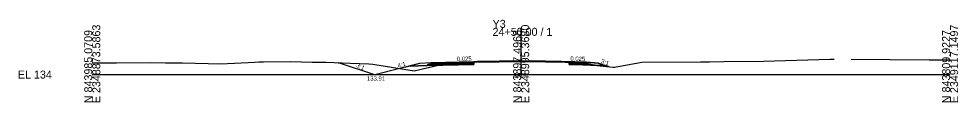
# Model space of a CAD drawing. Extents: x -26 to 2349107, y -10 to 844057.
# Drawn here: x -25.7 to 302.8, y 3490.3 to 3519.2 of the extents above; entities that cross this region are included whole.
import ezdxf

# ---------------------------------------------------------------- set-up
doc = ezdxf.new("R2010")
doc.units = 0
for name, color, linetype in [('Exist Cross Section Cell', 7, 'Continuous'), ('Exist XS Center Line Elevation Label', 7, 'Continuous'), ('Exist XS Ground Line', 7, 'Continuous'), ('Prop CMT Pvmt Course 1', 7, 'Continuous'), ('Prop CMT Pvmt Course 2', 7, 'Continuous'), ('Prop CMT Pvmt Course 3', 7, 'Continuous'), ('Prop CMT Pvmt Surface Shoulder', 7, 'Continuous'), ('Prop CMT Shld Paved Course 1', 7, 'Continuous'), ('Prop CMT Shld Paved Course 2', 7, 'Continuous'), ('Prop CMT Shld Paved Course 3', 7, 'Continuous'), ('Prop CMT Slope Grass', 7, 'Continuous'), ('Prop CMT Subgrade Earthwork', 7, 'Continuous'), ('Prop XS Ditch Standard Text', 7, 'Continuous'), ('Prop XS Earthwork Shape', 7, 'Continuous'), ('Prop XS SE Text', 7, 'Continuous'), ('Prop XS Side Slope Text', 7, 'Continuous')]:
    doc.layers.add(name, color=color, linetype=linetype)

msp = doc.modelspace()

# ---------------------------------------------------------------- linework, layer by layer
at = {"layer": 'Exist Cross Section Cell'}
for p, q in [((150, 3500), (150, 3516.36)), ((0, 3500), (150, 3500)), ((150, 3500), (300, 3500))]:
    msp.add_line(p, q, dxfattribs=at)
at = {"layer": 'Exist XS Ground Line'}
for points in [[(0, 3504.1), (6.44, 3504.1), (7.88, 3504.1), (8.44, 3504.1), (20.2, 3504.21), (25.57, 3504.17), (31.52, 3504.07), (44.99, 3503.75), (56.84, 3504.37), (58.27, 3504.46), (59.83, 3504.49), (69.47, 3504.56), (76.96, 3504.39), (81.78, 3504.33), (90.23, 3504.01), (96.69, 3503.79), (98.1, 3503.59), (112.58, 3501.32), (115.04, 3501.88), (122.59, 3503.67), (127.37, 3504.1), (129.08, 3504.29), (129.86, 3504.29), (131.71, 3504.36), (133.64, 3504.4), (134.74, 3504.42), (135.96, 3504.44), (137.7, 3504.46), (138.76, 3504.48), (140.26, 3504.5), (140.79, 3504.51), (142.36, 3504.51), (144.17, 3504.53), (144.55, 3504.54), (146.95, 3504.56), (147.66, 3504.57), (148.88, 3504.57), (150.02, 3504.57), (153.09, 3504.56), (156.16, 3504.54), (156.66, 3504.54), (157.37, 3504.53), (158.46, 3504.51), (159.26, 3504.5), (160.27, 3504.48), (161.66, 3504.45), (162.37, 3504.44), (164.11, 3504.41), (165.4, 3504.39), (165.7, 3504.39), (166.75, 3504.36), (167.07, 3504.36), (168.45, 3504.34), (169.18, 3504.32), (170.03, 3504.28), (170.77, 3504.26), (172.3, 3503.84), (173.28, 3503.68), (176.43, 3503.2), (182.18, 3502.63), (182.68, 3502.59), (192.18, 3504.31), (212.67, 3504.43), (213.32, 3504.44), (215.86, 3504.52), (220.84, 3504.63), (234.78, 3504.71), (257.93, 3505.43), (259.42, 3505.45)], [(265.41, 3505.44), (292.69, 3505.17), (300, 3505.15)]]:
    msp.add_lwpolyline(points, dxfattribs=at)
at = {"layer": 'Prop CMT Pvmt Course 1'}
for p, q in [((122.5, 3504.24), (122.5, 3503.99)), ((133.43, 3504.52), (133.43, 3504.27)), ((166.75, 3504.48), (166.75, 3504.23)), ((168.74, 3504.43), (168.74, 3504.18))]:
    msp.add_line(p, q, dxfattribs=at)
at = {"layer": 'Prop CMT Pvmt Course 2'}
for p, q in [((122.5, 3503.99), (122.5, 3503.66)), ((133.43, 3504.27), (133.43, 3503.93)), ((166.75, 3504.23), (166.75, 3503.9)), ((168.74, 3504.18), (168.74, 3503.85))]:
    msp.add_line(p, q, dxfattribs=at)
at = {"layer": 'Prop CMT Pvmt Course 3'}
for p, q in [((122.5, 3503.66), (122.5, 3503.29)), ((133.43, 3503.93), (133.43, 3503.56)), ((166.75, 3503.9), (166.75, 3503.53)), ((168.74, 3503.85), (168.74, 3503.48))]:
    msp.add_line(p, q, dxfattribs=at)
at = {"layer": 'Prop CMT Pvmt Surface Shoulder'}
for p, q in [((133.43, 3504.52), (118.5, 3504.14)), ((166.75, 3504.48), (168.74, 3504.43)), ((168.74, 3504.43), (172.9, 3504.33))]:
    msp.add_line(p, q, dxfattribs=at)
msp.add_lwpolyline([(133.43, 3504.52), (133.64, 3504.52), (134.74, 3504.54), (135.96, 3504.56), (137.7, 3504.59), (138.76, 3504.61), (140.26, 3504.63), (140.79, 3504.63), (142.35, 3504.64), (144.17, 3504.66), (144.55, 3504.66), (146.95, 3504.69), (147.66, 3504.69), (148.88, 3504.69), (150.02, 3504.69), (153.09, 3504.69), (156.16, 3504.67), (156.67, 3504.66), (157.37, 3504.65), (158.47, 3504.64), (159.26, 3504.63), (160.27, 3504.61), (161.66, 3504.58), (162.37, 3504.56), (164.11, 3504.54), (165.4, 3504.52), (165.7, 3504.51), (166.75, 3504.48)], dxfattribs=at)
at = {"layer": 'Prop CMT Shld Paved Course 1'}
for p, q in [((118.24, 3503.89), (133.43, 3504.27)), ((118.5, 3504.14), (118.24, 3503.89)), ((133.43, 3504.52), (118.5, 3504.14)), ((122.5, 3503.99), (122.5, 3504.24)), ((133.43, 3504.27), (133.43, 3504.52)), ((166.75, 3504.48), (168.74, 3504.43)), ((166.75, 3504.23), (166.75, 3504.48)), ((168.74, 3504.18), (166.75, 3504.23)), ((168.74, 3504.18), (168.74, 3504.43)), ((168.74, 3504.43), (172.9, 3504.33)), ((173.16, 3504.07), (168.74, 3504.18)), ((172.9, 3504.33), (173.16, 3504.07))]:
    msp.add_line(p, q, dxfattribs=at)
at = {"layer": 'Prop CMT Shld Paved Course 2'}
for p, q in [((117.9, 3503.55), (133.43, 3503.93)), ((118.24, 3503.89), (117.9, 3503.55)), ((133.43, 3504.27), (118.24, 3503.89)), ((122.5, 3503.66), (122.5, 3503.99)), ((133.43, 3503.93), (133.43, 3504.27)), ((166.75, 3504.23), (168.74, 3504.18)), ((166.75, 3503.9), (166.75, 3504.23)), ((168.74, 3503.85), (166.75, 3503.9)), ((168.74, 3503.85), (168.74, 3504.18)), ((168.74, 3504.18), (173.16, 3504.07)), ((173.5, 3503.73), (168.74, 3503.85)), ((173.16, 3504.07), (173.5, 3503.73))]:
    msp.add_line(p, q, dxfattribs=at)
at = {"layer": 'Prop CMT Shld Paved Course 3'}
for p, q in [((117.4, 3503.53), (117.02, 3503.15)), ((117.1, 3503.15), (133.43, 3503.56)), ((117.9, 3503.55), (117.4, 3503.53)), ((133.43, 3503.93), (117.9, 3503.55)), ((122.5, 3503.29), (122.5, 3503.66)), ((133.43, 3503.56), (133.43, 3503.93)), ((166.75, 3503.9), (168.74, 3503.85)), ((166.75, 3503.53), (166.75, 3503.9)), ((168.74, 3503.48), (166.75, 3503.53)), ((168.74, 3503.48), (168.74, 3503.85)), ((168.74, 3503.85), (173.5, 3503.73)), ((174.3, 3503.34), (168.74, 3503.48)), ((173.5, 3503.73), (174, 3503.72)), ((174, 3503.72), (174.38, 3503.34))]:
    msp.add_line(p, q, dxfattribs=at)
at = {"layer": 'Prop CMT Slope Grass'}
for p, q in [((98.83, 3499.91), (86.06, 3504.16)), ((114.5, 3503.82), (98.83, 3499.91)), ((118.5, 3504.14), (114.5, 3503.82)), ((172.9, 3504.33), (176.9, 3504.01)), ((176.9, 3504.01), (180.55, 3502.79))]:
    msp.add_line(p, q, dxfattribs=at)
at = {"layer": 'Prop CMT Subgrade Earthwork'}
for p, q in [((117.02, 3503.15), (111.22, 3503)), ((133.43, 3503.56), (117.02, 3503.15)), ((133.43, 3503.56), (133.43, 3504.39)), ((166.75, 3503.53), (166.75, 3504.36)), ((166.75, 3503.53), (168.74, 3503.48)), ((168.74, 3503.48), (174.38, 3503.34)), ((174.38, 3503.34), (179.29, 3503.21))]:
    msp.add_line(p, q, dxfattribs=at)
at = {"layer": 'Prop XS Earthwork Shape'}
for points in [[(90.23, 3504.01), (96.69, 3503.79), (98.1, 3503.59), (107.61, 3502.1), (98.83, 3499.91), (86.06, 3504.16)], [(120.8, 3503.24), (117.02, 3503.15), (111.22, 3503), (107.61, 3502.1), (112.58, 3501.32), (115.04, 3501.88)], [(133.43, 3504.52), (118.5, 3504.14), (114.5, 3503.82), (111.22, 3503), (117.02, 3503.15), (120.8, 3503.24), (122.59, 3503.67), (127.37, 3504.1), (129.08, 3504.29), (129.86, 3504.29), (131.71, 3504.36), (133.43, 3504.39), (133.64, 3504.4), (134.74, 3504.42), (135.96, 3504.44), (137.7, 3504.46), (138.76, 3504.48), (140.26, 3504.5), (140.79, 3504.51), (142.36, 3504.51), (144.17, 3504.53), (144.55, 3504.54), (146.95, 3504.56), (147.66, 3504.57), (148.88, 3504.57), (150.02, 3504.57), (153.09, 3504.56), (156.16, 3504.54), (156.66, 3504.54), (157.37, 3504.53), (158.46, 3504.51), (159.26, 3504.5), (160.27, 3504.48), (161.66, 3504.45), (162.37, 3504.44), (164.11, 3504.41), (165.4, 3504.39), (165.7, 3504.39), (166.75, 3504.36), (167.07, 3504.36), (168.45, 3504.34), (169.18, 3504.32), (170.03, 3504.28), (170.77, 3504.26), (172.3, 3503.84), (173.28, 3503.68), (175.78, 3503.3), (179.29, 3503.21), (176.9, 3504.01), (172.9, 3504.33), (168.74, 3504.43), (166.75, 3504.48), (165.7, 3504.51), (165.4, 3504.52), (164.11, 3504.54), (162.37, 3504.56), (161.66, 3504.58), (160.27, 3504.61), (159.26, 3504.63), (158.47, 3504.64), (157.37, 3504.65), (156.67, 3504.66), (156.16, 3504.67), (153.09, 3504.69), (150.02, 3504.69), (148.88, 3504.69), (147.66, 3504.69), (146.95, 3504.69), (144.55, 3504.66), (144.17, 3504.66), (142.35, 3504.64), (140.79, 3504.63), (140.26, 3504.63), (138.76, 3504.61), (137.7, 3504.59), (135.96, 3504.56), (134.74, 3504.54), (133.64, 3504.52)], [(133.43, 3503.56), (120.8, 3503.24), (122.59, 3503.67), (127.37, 3504.1), (129.08, 3504.29), (129.86, 3504.29), (131.71, 3504.36), (133.43, 3504.39)], [(174.38, 3503.34), (175.78, 3503.3), (173.28, 3503.68), (172.3, 3503.84), (170.77, 3504.26), (170.03, 3504.28), (169.18, 3504.32), (168.45, 3504.34), (167.07, 3504.36), (166.75, 3504.36), (166.75, 3503.53), (168.74, 3503.48)], [(175.78, 3503.3), (176.43, 3503.2), (180.55, 3502.79), (179.29, 3503.21)]]:
    msp.add_lwpolyline(points, close=True, dxfattribs=at)

# ---------------------------------------------------------------- texts
at = {"layer": 'Exist Cross Section Cell'}
for s, p in [('Y3', (140, 3516.36)), ('24+50.00 / 1', (140, 3513.56)), ('EL 134', (-26, 3498.6))]:
    msp.add_text(s, height=2.8, dxfattribs=at).set_placement(p)
for s, p in [('N 843985.0709', (0, 3490)), ('E 2348873.5863', (2.8, 3490)), ('N 843897.4968', (150, 3490)), ('E 2348995.3680', (152.8, 3490)), ('N 843809.9227', (300, 3490)), ('E 2349117.1497', (302.8, 3490))]:
    msp.add_text(s, height=2.8, rotation=90, dxfattribs=at).set_placement(p)
at = {"layer": 'Exist XS Center Line Elevation Label'}
msp.add_text('138.57', height=1.2, dxfattribs=at).set_placement((147.55, 3498.97))
at = {"layer": 'Prop XS Ditch Standard Text'}
msp.add_text('133.91', height=1.5, dxfattribs=at).set_placement((96.07, 3497.88))
at = {"layer": 'Prop XS SE Text'}
for rotation, p in [(1.4321, (127.52, 3504.73)), (358.2177, (167.2, 3504.88))]:
    msp.add_text('0.025', height=1.5, rotation=rotation, dxfattribs=at).set_placement(p)
at = {"layer": 'Prop XS Side Slope Text'}
for s, rotation, p in [('3:1', 340.7803, (177.75, 3504.12)), ('3:1', 334.1575, (92.2, 3502.74)), ('4:1', 14.0362, (106.95, 3502.39))]:
    msp.add_text(s, height=1.5, rotation=rotation, dxfattribs=at).set_placement(p)

doc.saveas('drawing.dxf')
